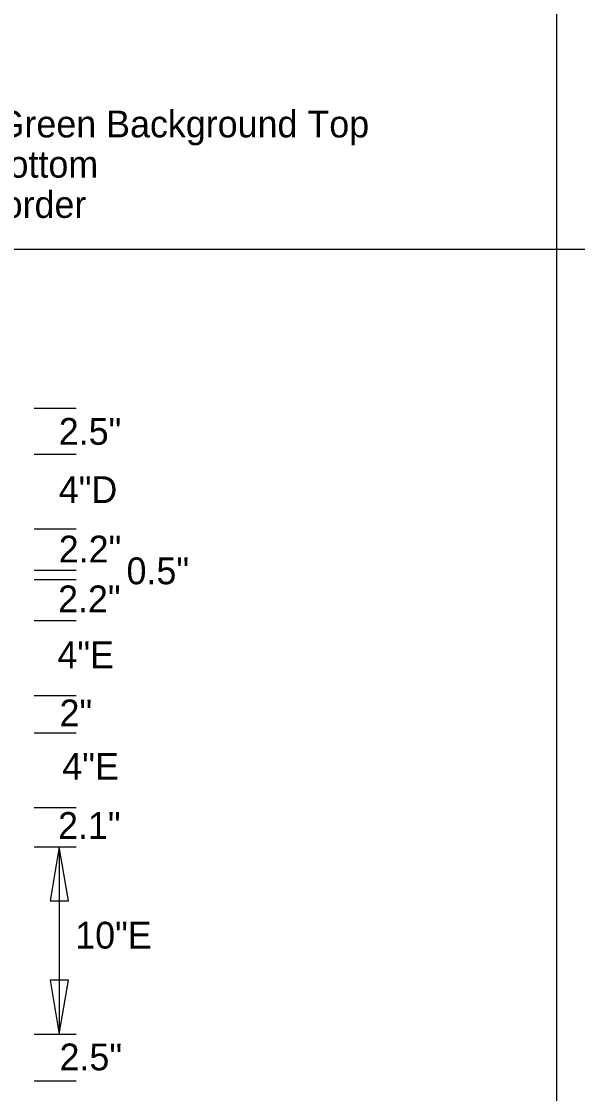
# Model space of a CAD drawing. Extents: x 0 to 770, y 0 to 495.
# Drawn here: x 507.6 to 580.2, y 219.9 to 359.7 of the extents above; entities that cross this region are included whole.
import ezdxf

# ---------------------------------------------------------------- set-up
doc = ezdxf.new("R2010")
doc.units = 0
for name, color, linetype in [('Dimension', 7, 'Continuous'), ('GSDims', 7, 'Continuous'), ('SheetLines_dp', 7, 'Continuous'), ('TextStructures', 7, 'Continuous')]:
    doc.layers.add(name, color=color, linetype=linetype)

msp = doc.modelspace()

# ---------------------------------------------------------------- linework, layer by layer
at = {"layer": 'Dimension'}
for points in [[(512.5, 252.05), (511.32, 245.03), (513.69, 245.03)], [(512.5, 227.64), (513.69, 234.66), (511.32, 234.66)]]:
    msp.add_lwpolyline(points, close=True, dxfattribs=at)
at = {"layer": 'GSDims'}
for p, q in [((509.21, 309.27), (514.7, 309.27)), ((509.21, 303.29), (514.7, 303.29)), ((509.21, 303.29), (514.7, 303.29)), ((509.21, 293.53), (514.7, 293.53)), ((509.21, 293.53), (514.7, 293.53)), ((509.21, 288.16), (514.7, 288.16)), ((509.21, 288.16), (514.7, 288.16)), ((509.21, 286.94), (514.7, 286.94)), ((509.21, 286.94), (514.7, 286.94)), ((509.21, 281.57), (514.7, 281.57)), ((509.21, 281.57), (514.7, 281.57)), ((509.21, 271.81), (514.7, 271.81)), ((509.21, 271.81), (514.7, 271.81)), ((509.21, 266.93), (514.7, 266.93)), ((509.21, 266.93), (514.7, 266.93)), ((509.21, 257.17), (514.7, 257.17)), ((509.21, 257.17), (514.7, 257.17)), ((509.21, 252.05), (514.7, 252.05)), ((509.21, 252.05), (514.7, 252.05)), ((512.5, 252.05), (512.5, 227.64)), ((509.21, 227.64), (514.7, 227.64)), ((509.21, 227.64), (514.7, 227.64)), ((509.21, 221.54), (514.7, 221.54))]:
    msp.add_line(p, q, dxfattribs=at)
at = {"layer": 'SheetLines_dp'}
for p, q in [((577.5, 0), (577.5, 495)), ((0, 330), (770, 330))]:
    msp.add_line(p, q, dxfattribs=at)

# ---------------------------------------------------------------- texts
at = {"layer": 'TextStructures'}
for s, p in [('Fluorescent Yellow-Green Background Top   ', (463.22, 344.6)), ('White Background Bottom', (463.22, 339.35)), ('Black Legend and Border', (463.22, 334.1)), ('2.5"', (512.44, 304.5)), ('4"D', (512.44, 296.9)), ('2.2"', (512.44, 289.15)), ('0.5"', (521.29, 286.31)), ('2.2"', (512.35, 282.65)), ('4"E', (512.26, 275.36)), ('2"', (512.54, 267.77)), ('4"E', (512.9, 260.81)), ('2.1"', (512.35, 253.09)), ('10"E', (514.59, 238.78)), ('2.5"', (512.54, 222.9))]:
    msp.add_text(s, height=3.5, dxfattribs=at).set_placement(p)

doc.saveas('drawing.dxf')
